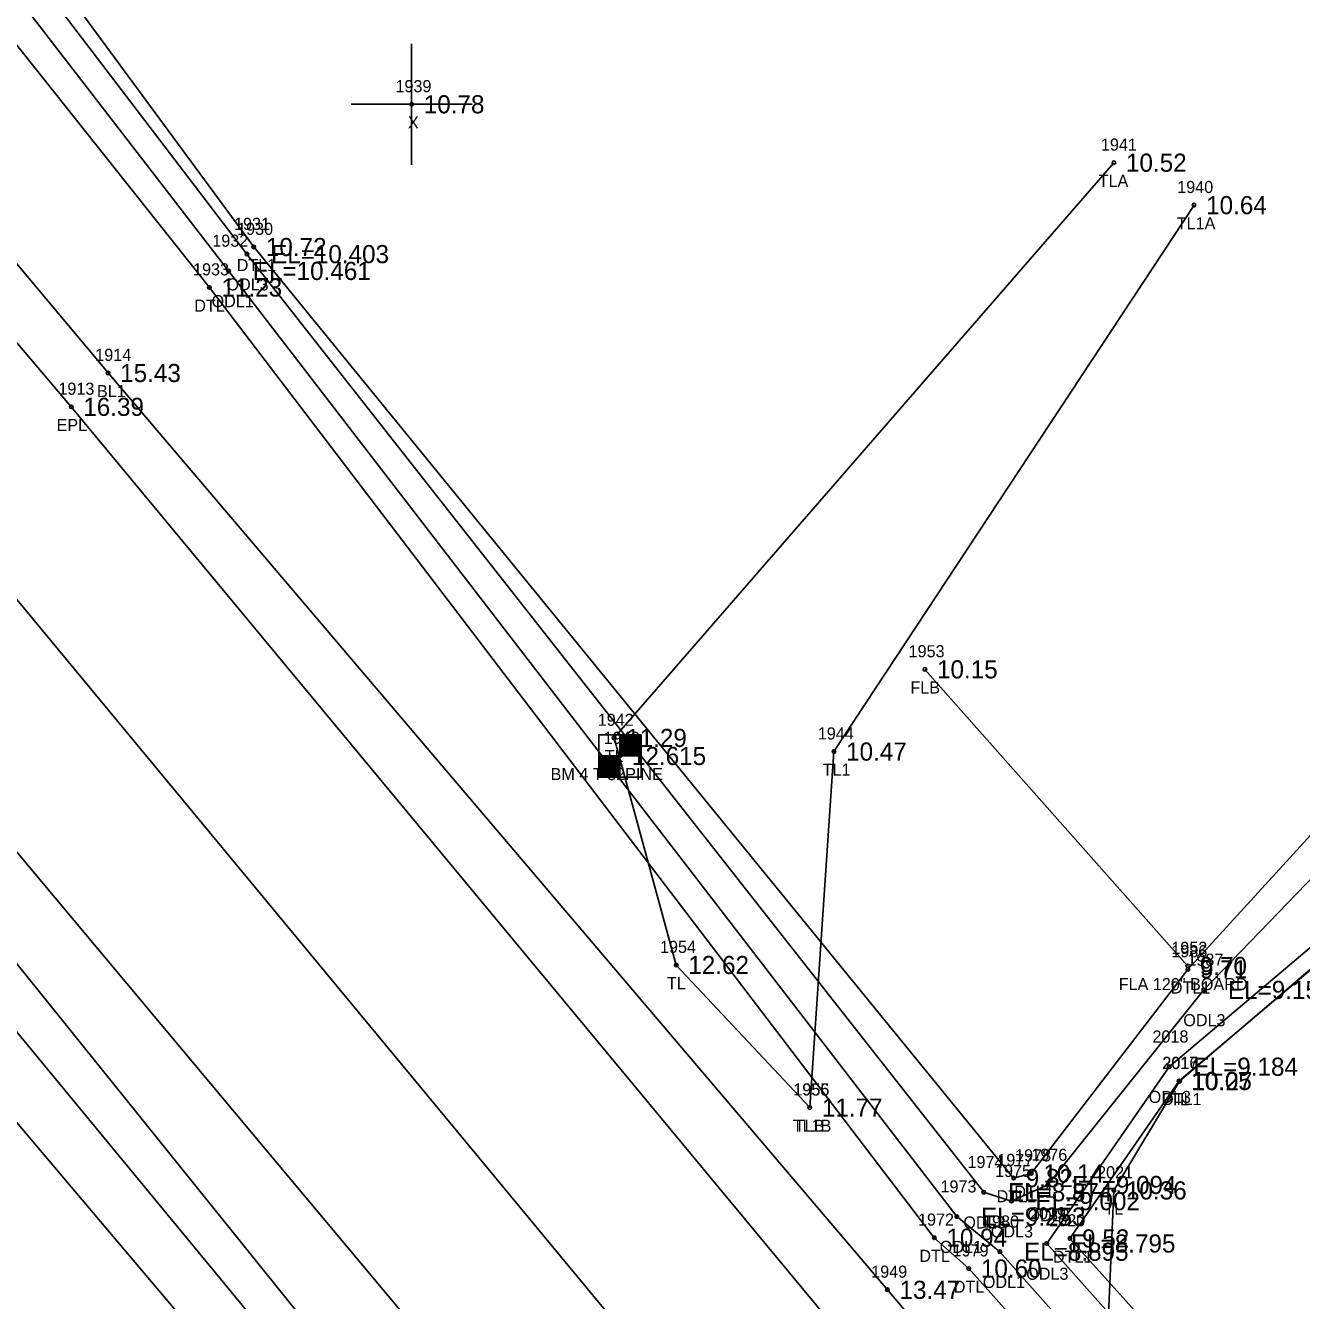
# Model space of a CAD drawing. Extents: x 2042211 to 2045853, y 303080 to 309569.
# Drawn here: x 2044074.2 to 2044179.7, y 305120.2 to 305225.7 of the extents above; entities that cross this region are included whole.
import ezdxf

# ---------------------------------------------------------------- set-up
doc = ezdxf.new("R2010")
doc.units = 0
for name, color, linetype in [('BR_500YR_SCOUR', 7, 'Continuous'), ('RD_DTM_BkLn1', 7, 'Continuous'), ('RD_DTM_BkLn2', 7, 'Continuous'), ('RD_DTM_BkLn_txCode', 7, 'Continuous'), ('RD_EX_Fence_Other_txCode', 7, 'Continuous'), ('RD_EX_H2O', 7, 'Continuous'), ('RD_EX_H2O_txCode', 7, 'Continuous'), ('RD_EX_Misc', 7, 'Continuous'), ('RD_EX_Misc_txCode', 7, 'Continuous'), ('RD_EX_Road', 7, 'Continuous'), ('RD_EX_Road_txCode', 7, 'Continuous'), ('RD_EX_TX_Fence_Other_ELEV', 7, 'Continuous'), ('RD_EX_TX_H2O_ELEV', 7, 'Continuous'), ('RD_EX_TX_Misc_ELEV', 7, 'Continuous'), ('RD_EX_TX_Road_ELEV', 7, 'Continuous'), ('RD_EX_TX_VEG_ELEV', 7, 'Continuous'), ('RD_EX_VEG_txCode', 7, 'Continuous'), ('RD_HC_Survey_ELEV', 7, 'Continuous'), ('RD_HC_Survey_txCode', 7, 'Continuous'), ('RD_SMD_Locator', 7, 'Continuous')]:
    doc.layers.add(name, color=color, linetype=linetype)

msp = doc.modelspace()

# ---------------------------------------------------------------- linework, layer by layer
at = {"layer": 'BR_500YR_SCOUR'}
for p, q in [((2044170.31, 305147.91), (2044148.58, 305172.44)), ((2044123.35, 305167.03), (2044123.35, 305163.53)), ((2044123.37, 305167.03), (2044123.37, 305165.28)), ((2044123.39, 305167.03), (2044123.39, 305165.28)), ((2044123.42, 305167.03), (2044123.42, 305165.28)), ((2044123.44, 305167.03), (2044123.44, 305165.28)), ((2044123.47, 305167.03), (2044123.47, 305165.28)), ((2044123.49, 305167.03), (2044123.49, 305165.28)), ((2044123.52, 305167.03), (2044123.52, 305165.28)), ((2044123.54, 305167.03), (2044123.54, 305165.28)), ((2044123.57, 305167.03), (2044123.57, 305165.28)), ((2044123.59, 305167.03), (2044123.59, 305165.28)), ((2044123.62, 305167.03), (2044123.62, 305165.28)), ((2044123.64, 305167.03), (2044123.64, 305165.28)), ((2044123.67, 305167.03), (2044123.67, 305165.28)), ((2044123.69, 305167.03), (2044123.69, 305165.28)), ((2044123.72, 305167.03), (2044123.72, 305165.28)), ((2044123.74, 305167.03), (2044123.74, 305165.28)), ((2044123.77, 305167.03), (2044123.77, 305165.28)), ((2044123.79, 305167.03), (2044123.79, 305165.28)), ((2044123.82, 305167.03), (2044123.82, 305165.28)), ((2044123.84, 305167.03), (2044123.84, 305165.28)), ((2044123.87, 305167.03), (2044123.87, 305165.28)), ((2044123.89, 305167.03), (2044123.89, 305165.28)), ((2044123.91, 305167.03), (2044123.91, 305165.28)), ((2044123.94, 305167.03), (2044123.94, 305165.28)), ((2044123.96, 305167.03), (2044123.96, 305165.28)), ((2044123.99, 305167.03), (2044123.99, 305165.28)), ((2044124.01, 305167.03), (2044124.01, 305165.28)), ((2044124.04, 305167.03), (2044124.04, 305165.28)), ((2044124.06, 305167.03), (2044124.06, 305165.28)), ((2044124.09, 305167.03), (2044124.09, 305165.28)), ((2044124.11, 305167.03), (2044124.11, 305165.28)), ((2044124.14, 305167.03), (2044124.14, 305165.28)), ((2044124.16, 305167.03), (2044124.16, 305165.28)), ((2044124.19, 305167.03), (2044124.19, 305165.28)), ((2044124.21, 305167.03), (2044124.21, 305165.28)), ((2044124.24, 305167.03), (2044124.24, 305165.28)), ((2044124.26, 305167.03), (2044124.26, 305165.28)), ((2044124.29, 305167.03), (2044124.29, 305165.28)), ((2044124.31, 305167.03), (2044124.31, 305165.28)), ((2044124.34, 305167.03), (2044124.34, 305165.28)), ((2044124.36, 305167.03), (2044124.36, 305165.28)), ((2044124.38, 305167.03), (2044124.38, 305165.28)), ((2044124.41, 305167.03), (2044124.41, 305165.28)), ((2044124.43, 305167.03), (2044124.43, 305165.28)), ((2044124.46, 305167.03), (2044124.46, 305165.28)), ((2044124.48, 305167.03), (2044124.48, 305165.28)), ((2044124.51, 305167.03), (2044124.51, 305165.28)), ((2044124.53, 305167.03), (2044124.53, 305165.28)), ((2044124.56, 305167.03), (2044124.56, 305165.28)), ((2044124.58, 305167.03), (2044124.58, 305165.28)), ((2044124.61, 305167.03), (2044124.61, 305165.28)), ((2044124.63, 305167.03), (2044124.63, 305165.28)), ((2044124.66, 305167.03), (2044124.66, 305165.28)), ((2044124.68, 305167.03), (2044124.68, 305165.28)), ((2044124.71, 305167.03), (2044124.71, 305165.28)), ((2044124.73, 305167.03), (2044124.73, 305165.28)), ((2044124.76, 305167.03), (2044124.76, 305165.28)), ((2044124.78, 305167.03), (2044124.78, 305165.28)), ((2044124.81, 305167.03), (2044124.81, 305165.28)), ((2044124.83, 305167.03), (2044124.83, 305165.28)), ((2044124.86, 305167.03), (2044124.86, 305165.28)), ((2044124.88, 305167.03), (2044124.88, 305165.28)), ((2044124.9, 305167.03), (2044124.9, 305165.28)), ((2044124.93, 305167.03), (2044124.93, 305165.28)), ((2044124.95, 305167.03), (2044124.95, 305165.28)), ((2044124.98, 305167.03), (2044124.98, 305165.28)), ((2044125, 305167.03), (2044125, 305165.28)), ((2044125.03, 305167.03), (2044125.03, 305165.28)), ((2044125.05, 305167.03), (2044125.05, 305165.28)), ((2044125.08, 305167.03), (2044125.08, 305165.28)), ((2044125.1, 305165.28), (2044121.6, 305165.28)), ((2044121.6, 305165.28), (2044121.6, 305163.53)), ((2044121.63, 305165.28), (2044121.63, 305163.53)), ((2044121.65, 305165.28), (2044121.65, 305163.53)), ((2044121.68, 305165.28), (2044121.68, 305163.53)), ((2044121.7, 305165.28), (2044121.7, 305163.53)), ((2044121.73, 305165.28), (2044121.73, 305163.53)), ((2044121.75, 305165.28), (2044121.75, 305163.53)), ((2044121.78, 305165.28), (2044121.78, 305163.53)), ((2044121.8, 305165.28), (2044121.8, 305163.53)), ((2044121.83, 305165.28), (2044121.83, 305163.53)), ((2044121.85, 305165.28), (2044121.85, 305163.53)), ((2044121.87, 305165.28), (2044121.87, 305163.53)), ((2044121.9, 305165.28), (2044121.9, 305163.53)), ((2044121.92, 305165.28), (2044121.92, 305163.53)), ((2044121.95, 305165.28), (2044121.95, 305163.53)), ((2044121.97, 305165.28), (2044121.97, 305163.53)), ((2044122, 305165.28), (2044122, 305163.53)), ((2044122.02, 305165.28), (2044122.02, 305163.53)), ((2044122.05, 305165.28), (2044122.05, 305163.53)), ((2044122.07, 305165.28), (2044122.07, 305163.53)), ((2044122.1, 305165.28), (2044122.1, 305163.53)), ((2044122.12, 305165.28), (2044122.12, 305163.53)), ((2044122.15, 305165.28), (2044122.15, 305163.53)), ((2044122.17, 305165.28), (2044122.17, 305163.53)), ((2044122.2, 305165.28), (2044122.2, 305163.53)), ((2044122.22, 305165.28), (2044122.22, 305163.53)), ((2044122.25, 305165.28), (2044122.25, 305163.53)), ((2044122.27, 305165.28), (2044122.27, 305163.53)), ((2044122.3, 305165.28), (2044122.3, 305163.53)), ((2044122.32, 305165.28), (2044122.32, 305163.53)), ((2044122.34, 305165.28), (2044122.34, 305163.53)), ((2044122.37, 305165.28), (2044122.37, 305163.53)), ((2044122.39, 305165.28), (2044122.39, 305163.53)), ((2044122.42, 305165.28), (2044122.42, 305163.53)), ((2044122.44, 305165.28), (2044122.44, 305163.53)), ((2044122.47, 305165.28), (2044122.47, 305163.53)), ((2044122.49, 305165.28), (2044122.49, 305163.53)), ((2044122.52, 305165.28), (2044122.52, 305163.53)), ((2044122.54, 305165.28), (2044122.54, 305163.53)), ((2044122.57, 305165.28), (2044122.57, 305163.53)), ((2044122.59, 305165.28), (2044122.59, 305163.53)), ((2044122.62, 305165.28), (2044122.62, 305163.53)), ((2044122.64, 305165.28), (2044122.64, 305163.53)), ((2044122.67, 305165.28), (2044122.67, 305163.53)), ((2044122.69, 305165.28), (2044122.69, 305163.53)), ((2044122.72, 305165.28), (2044122.72, 305163.53)), ((2044122.74, 305165.28), (2044122.74, 305163.53)), ((2044122.77, 305165.28), (2044122.77, 305163.53)), ((2044122.79, 305165.28), (2044122.79, 305163.53)), ((2044122.82, 305165.28), (2044122.82, 305163.53)), ((2044122.84, 305165.28), (2044122.84, 305163.53)), ((2044122.86, 305165.28), (2044122.86, 305163.53)), ((2044122.89, 305165.28), (2044122.89, 305163.53)), ((2044122.91, 305165.28), (2044122.91, 305163.53)), ((2044122.94, 305165.28), (2044122.94, 305163.53)), ((2044122.96, 305165.28), (2044122.96, 305163.53)), ((2044122.99, 305165.28), (2044122.99, 305163.53)), ((2044123.01, 305165.28), (2044123.01, 305163.53)), ((2044123.04, 305165.28), (2044123.04, 305163.53)), ((2044123.06, 305165.28), (2044123.06, 305163.53)), ((2044123.09, 305165.28), (2044123.09, 305163.53)), ((2044123.11, 305165.28), (2044123.11, 305163.53)), ((2044123.14, 305165.28), (2044123.14, 305163.53)), ((2044123.16, 305165.28), (2044123.16, 305163.53)), ((2044123.19, 305165.28), (2044123.19, 305163.53)), ((2044123.21, 305165.28), (2044123.21, 305163.53)), ((2044123.24, 305165.28), (2044123.24, 305163.53)), ((2044123.26, 305165.28), (2044123.26, 305163.53)), ((2044123.29, 305165.28), (2044123.29, 305163.53)), ((2044123.31, 305165.28), (2044123.31, 305163.53)), ((2044123.33, 305165.28), (2044123.33, 305163.53))]:
    msp.add_line(p, q, dxfattribs=at)
for points in [[(2043981.22, 305231.74), (2043985.09, 305231.71), (2043988, 305235.21), (2044050.29, 305170.52), (2044112.48, 305095.16), (2044104.33, 305083.55)], [(2044164.21, 305214.34), (2044122.87, 305166.77), (2044128.01, 305147.99), (2044139.06, 305136.2)], [(2044170.84, 305210.83), (2044141.06, 305165.64), (2044139.06, 305136.2)], [(2044203.29, 305185.8), (2044187.09, 305153.29), (2044169.64, 305138.38), (2044164.21, 305129.35), (2044163.7, 305117.76), (2044206.63, 305057.39), (2044230.52, 305052.69), (2044229.62, 305068.74), (2044231.4, 305092.87), (2044226.11, 305140.65)]]:
    msp.add_lwpolyline(points, dxfattribs=at)
msp.add_lwpolyline([(2044125.1, 305167.03), (2044121.6, 305167.03), (2044121.6, 305163.53), (2044125.1, 305163.53)], close=True, dxfattribs=at)
for centre in [(2044164.21, 305214.34), (2044170.84, 305210.83), (2044122.87, 305166.77), (2044123.35, 305165.28), (2044141.06, 305165.64), (2044128.01, 305147.99), (2044169.64, 305138.38), (2044139.06, 305136.2), (2044164.21, 305129.35)]:
    msp.add_circle(centre, 0.15, dxfattribs=at)
at = {"layer": 'RD_DTM_BkLn1'}
for points in [[(2043537.57, 305841.2), (2043543.07, 305834.82), (2043547.67, 305836.32), (2043557.54, 305825.5), (2043571.92, 305809.49), (2043633.83, 305732.88), (2043699.09, 305656.29), (2043762.93, 305580.55), (2043827.21, 305502.36), (2043888.69, 305425.33), (2043954.53, 305349.45), (2044014.08, 305277.47), (2044018.49, 305276.45), (2044019.61, 305275.44), (2044023.1, 305269.64), (2044024.11, 305264.85), (2044081.02, 305196.95), (2044145.48, 305121.13), (2044210.56, 305044.49), (2044273.6, 304967.95), (2044321.18, 304912.75), (2044337.82, 304895.78)], [(2043528.91, 305830.2), (2043556.35, 305797.19), (2043619.96, 305720.85), (2043684.02, 305644.21), (2043747.98, 305567.9), (2043812.35, 305491.13), (2043876, 305414.64), (2043940.22, 305337.83), (2044003.86, 305261.82), (2044067.88, 305184.94), (2044131, 305108.73), (2044195.62, 305032.03), (2044259.59, 304955.88), (2044323.63, 304879.52), (2044387.48, 304802.4), (2044451.92, 304725.21), (2044515.94, 304648.42), (2044581.15, 304571.52), (2044645.01, 304495.17), (2044708.42, 304418.52), (2044772.84, 304341.13)], [(2043798.36, 305479.17), (2043862.32, 305402.71), (2043926.37, 305326.69), (2043989.74, 305249.79), (2043988.33, 305246.75), (2043991.19, 305243.51), (2043994.75, 305243.65), (2044053.09, 305173.37), (2044116.28, 305094.9), (2044180.2, 305019.52), (2044245.63, 304943.51), (2044308.37, 304866.05), (2044373.1, 304789.96), (2044438.35, 304712.62), (2044501.57, 304636.05), (2044528.47, 304600.32), (2044565.87, 304558.85), (2044630.47, 304482.97), (2044694.06, 304405.2), (2044697.06, 304397.81), (2044701.81, 304392.08), (2044707.96, 304388.87), (2044759.04, 304329.78)]]:
    msp.add_lwpolyline(points, dxfattribs=at)
at = {"layer": 'RD_DTM_BkLn2'}
msp.add_lwpolyline([(2043985.04, 305231.73), (2044045.47, 305168.04), (2044111.06, 305090.52)], dxfattribs=at)
at = {"layer": 'RD_EX_H2O'}
for points in [[(2043695.41, 305785.95), (2043753.23, 305702.74), (2043816.84, 305621.67), (2043878.98, 305542.47), (2043936.42, 305466.41), (2044001.08, 305383.06), (2044036.64, 305336.24), (2044042.32, 305312.25), (2044044.08, 305296.68), (2044037.04, 305284.58), (2044037.23, 305281.89), (2044040.11, 305279.62), (2044044.74, 305276.06), (2044050.89, 305261.28), (2044092.5, 305206.78), (2044153.45, 305129.2), (2044155.72, 305128.46), (2044158.75, 305129.8), (2044171.64, 305145.93), (2044183.17, 305157.87), (2044199.16, 305188.17), (2044208.66, 305215.31)], [(2044033.22, 305275.98), (2044035.9, 305278.5), (2044040.04, 305277.28), (2044042.29, 305273.95), (2044048.6, 305260.29), (2044090.99, 305205.39), (2044151.22, 305127.18), (2044154.78, 305124.28), (2044202.92, 305070.22), (2044216.63, 305053.71), (2044279.58, 304974.12), (2044337.99, 304907.57), (2044344.68, 304901.99)], [(2044036.31, 305275.77), (2044038.93, 305275.76), (2044040.37, 305274.17), (2044045.78, 305258.87), (2044089.4, 305204.02), (2044149.36, 305125.44), (2044152.21, 305122.89), (2044203.11, 305065.8), (2044214.18, 305051.6), (2044278.81, 304973.18), (2044336.46, 304906.31), (2044343.82, 304899.94), (2044347.6, 304901.86)], [(2044052.64, 305262.28), (2044093.07, 305207.37), (2044155.92, 305130.37), (2044157.38, 305130.75), (2044170.33, 305147.63), (2044181.38, 305159.73), (2044197.15, 305188.95), (2044208.08, 305219.28), (2044210.72, 305219.24), (2044215.12, 305217.08), (2044202.83, 305184.83), (2044185.43, 305151.79), (2044169.6, 305138.4), (2044160.58, 305125.38), (2044211.54, 305068.64), (2044219.9, 305056.44), (2044285.19, 304978.84), (2044339.94, 304911.4), (2044347.53, 304904.82), (2044347.6, 304901.86)], [(2044211.75, 305214.4), (2044200.54, 305185.5), (2044183.75, 305152.21), (2044168.79, 305139.58), (2044158.66, 305124.96), (2044210.53, 305066.67), (2044218.51, 305055.53), (2044282.21, 304976.06), (2044339.42, 304909.19), (2044345.98, 304903.69)]]:
    msp.add_lwpolyline(points, dxfattribs=at)
at = {"layer": 'RD_EX_Misc'}
for p, q in [((2044106.13, 305214.17), (2044106.13, 305224.17)), ((2044101.13, 305219.17), (2044111.13, 305219.17))]:
    msp.add_line(p, q, dxfattribs=at)
at = {"layer": 'RD_EX_Road'}
for points in [[(2043522.11, 305820), (2043547.67, 305789.85), (2043610.72, 305713.32), (2043674.95, 305636.32), (2043738.18, 305559.62), (2043802.42, 305482.71), (2043865.72, 305405.84), (2043929.53, 305328.85), (2043994.13, 305253.28), (2044057.4, 305176.5), (2044121.27, 305100.2), (2044185.29, 305023.54), (2044249.56, 304947.28), (2044313.31, 304870.31), (2044377.09, 304793.29), (2044442, 304716.26), (2044505.92, 304639.55), (2044570.44, 304562.35), (2044634.61, 304485.93), (2044698.46, 304409.27), (2044762.46, 304332.37)], [(2044013.41, 305270.34), (2044077.97, 305194.15), (2044141.4, 305117.67), (2044205.92, 305040.83), (2044269.54, 304964.65), (2044331.73, 304891.04), (2044335.22, 304889.2), (2044346.01, 304875.31), (2044356.18, 304867.61), (2044370.01, 304868.14), (2044386.83, 304866.36), (2044389.44, 304849.53), (2044390.71, 304830.73), (2044393.77, 304818.44), (2044395.5, 304814.18), (2044398.16, 304811.09), (2044461.8, 304734.03), (2044526.04, 304657.6), (2044591.28, 304580.23), (2044655.29, 304503.62), (2044718.26, 304427.32), (2044783.13, 304349.86)]]:
    msp.add_lwpolyline(points, dxfattribs=at)
at = {"layer": 'RD_SMD_Locator'}
for centre in [(2044106.13, 305219.17), (2044093.07, 305207.37), (2044092.5, 305206.78), (2044090.99, 305205.39), (2044089.4, 305204.02), (2044081.02, 305196.95), (2044077.97, 305194.15), (2044148.58, 305172.44), (2044170.31, 305147.91), (2044170.33, 305147.63), (2044171.64, 305145.93), (2044168.79, 305139.58), (2044169.6, 305138.4), (2044139.06, 305136.2), (2044155.92, 305130.37), (2044157.38, 305130.75), (2044153.45, 305129.2), (2044158.75, 305129.8), (2044155.72, 305128.46), (2044151.22, 305127.18), (2044149.36, 305125.44), (2044158.66, 305124.96), (2044160.58, 305125.38), (2044154.78, 305124.28), (2044152.21, 305122.89), (2044145.48, 305121.13)]:
    msp.add_circle(centre, 0.15, dxfattribs=at)

# ---------------------------------------------------------------- texts
at = {"layer": 'RD_DTM_BkLn_txCode'}
for s, p in [('1914', (2044079.96, 305197.95)), ('BL1', (2044080.1, 305194.95)), ('1949', (2044144.14, 305122.13))]:
    msp.add_text(s, height=1, dxfattribs=at).set_placement(p)
at = {"layer": 'RD_EX_Fence_Other_txCode'}
for s, p in [('1953', (2044147.23, 305173.44)), ('FLB', (2044147.38, 305170.44)), ('1952', (2044168.96, 305148.91)), ('FLA 120" BOARD', (2044164.61, 305145.91))]:
    msp.add_text(s, height=1, dxfattribs=at).set_placement(p)
at = {"layer": 'RD_EX_H2O_txCode'}
for s, p in [('1931', (2044091.44, 305208.78)), ('1930', (2044091.69, 305208.37)), ('1932', (2044089.64, 305207.39)), ('DTL1', (2044091.66, 305205.37)), ('1933', (2044088.05, 305205.02)), ('ODL3', (2044090.81, 305203.78)), ('ODL1', (2044089.58, 305202.39)), ('DTL', (2044088.15, 305202.02)), ('1986', (2044168.96, 305148.63)), ('1987', (2044170.29, 305147.93)), ('DTL1', (2044168.92, 305145.63)), ('ODL3', (2044169.95, 305142.93)), ('2018', (2044167.4, 305141.58)), ('2017', (2044168.21, 305139.4)), ('ODL3', (2044167.09, 305136.58)), ('DTL1', (2044168.19, 305136.4)), ('1978', (2044156.04, 305131.75)), ('1976', (2044157.38, 305131.8)), ('1974', (2044152.1, 305131.2)), ('1975', (2044154.38, 305130.46)), ('1977', (2044154.57, 305131.37)), ('1973', (2044149.87, 305129.18)), ('DTL1', (2044154.51, 305128.37)), ('DTL1', (2044155.97, 305128.75)), ('1972', (2044148.01, 305126.44)), ('ODL3', (2044151.76, 305126.2)), ('1980', (2044153.39, 305126.28)), ('ODL3', (2044157.06, 305126.8)), ('2019', (2044157.27, 305126.96)), ('2020', (2044158.87, 305126.38)), ('ODL3', (2044154.03, 305125.46)), ('ODL1', (2044149.81, 305124.18)), ('DTL', (2044148.12, 305123.44)), ('1979', (2044150.87, 305123.89)), ('DTL1', (2044159.17, 305123.38)), ('ODL3', (2044156.96, 305121.96)), ('DTL', (2044150.97, 305120.89)), ('ODL1', (2044153.37, 305121.28))]:
    msp.add_text(s, height=1, dxfattribs=at).set_placement(p)
at = {"layer": 'RD_EX_Misc_txCode'}
for s, p in [('1939', (2044104.79, 305220.17)), ('X', (2044105.82, 305217.17))]:
    msp.add_text(s, height=1, dxfattribs=at).set_placement(p)
at = {"layer": 'RD_EX_Road_txCode'}
for s, p in [('1913', (2044076.91, 305195.15)), ('EPL', (2044076.76, 305192.15))]:
    msp.add_text(s, height=1, dxfattribs=at).set_placement(p)
at = {"layer": 'RD_EX_TX_Fence_Other_ELEV'}
for s, p in [('10.15', (2044149.58, 305171.69)), ('9.70', (2044171.31, 305147.16))]:
    msp.add_text(s, height=1.5, dxfattribs=at).set_placement(p)
at = {"layer": 'RD_EX_TX_H2O_ELEV'}
for s, p in [('10.72', (2044094.07, 305206.62)), ('EL=10.403', (2044094.5, 305206.03)), ('EL=10.461', (2044092.99, 305204.64)), ('11.23', (2044090.4, 305203.27)), ('9.71', (2044171.33, 305146.88)), ('EL=9.150', (2044173.64, 305145.18)), ('EL=9.184', (2044170.79, 305138.83)), ('10.05', (2044170.6, 305137.65)), ('10.14', (2044158.38, 305130)), ('9.82', (2044156.92, 305129.62)), ('EL=9.094', (2044160.75, 305129.05)), ('EL=8.874', (2044155.45, 305128.45)), ('EL=9.002', (2044157.72, 305127.71)), ('EL=9.253', (2044153.22, 305126.43)), ('10.94', (2044150.36, 305124.69)), ('9.52', (2044161.58, 305124.63)), ('EL=8.895', (2044156.78, 305123.53)), ('EL=8.795', (2044160.66, 305124.21)), ('10.60', (2044153.21, 305122.14))]:
    msp.add_text(s, height=1.5, dxfattribs=at).set_placement(p)
at = {"layer": 'RD_EX_TX_Misc_ELEV'}
for s, p in [('10.78', (2044107.13, 305218.42)), ('15.43', (2044082.02, 305196.2)), ('13.47', (2044146.48, 305120.38))]:
    msp.add_text(s, height=1.5, dxfattribs=at).set_placement(p)
at = {"layer": 'RD_EX_TX_Road_ELEV'}
msp.add_text('16.39', height=1.5, dxfattribs=at).set_placement((2044078.97, 305193.4))
at = {"layer": 'RD_EX_TX_VEG_ELEV'}
for s, p in [('10.52', (2044165.21, 305213.59)), ('10.64', (2044171.84, 305210.08)), ('11.29', (2044123.87, 305166.02)), ('10.47', (2044142.06, 305164.89)), ('12.62', (2044129.01, 305147.24)), ('10.27', (2044170.64, 305137.63)), ('11.77', (2044140.06, 305135.45)), ('11.77', (2044140.06, 305135.45)), ('10.36', (2044165.21, 305128.6))]:
    msp.add_text(s, height=1.5, dxfattribs=at).set_placement(p)
at = {"layer": 'RD_EX_VEG_txCode'}
for s, p in [('1941', (2044163.14, 305215.34)), ('TLA', (2044162.95, 305212.34)), ('1940', (2044169.45, 305211.83)), ('TL1A', (2044169.41, 305208.83)), ('1942', (2044121.52, 305167.77)), ('1944', (2044139.72, 305166.64)), ('TL', (2044122.1, 305164.77)), ('TL1', (2044140.12, 305163.64)), ('1954', (2044126.67, 305148.99)), ('TL', (2044127.24, 305145.99)), ('2016', (2044168.23, 305139.38)), ('1956', (2044137.69, 305137.2)), ('1955', (2044137.71, 305137.2)), ('TL', (2044168.87, 305136.38)), ('TL1B', (2044137.65, 305134.2)), ('TLB', (2044137.81, 305134.2)), ('2021', (2044162.82, 305130.35)), ('TL', (2044163.43, 305127.35))]:
    msp.add_text(s, height=1, dxfattribs=at).set_placement(p)
at = {"layer": 'RD_HC_Survey_ELEV'}
msp.add_text('12.615', height=1.5, dxfattribs=at).set_placement((2044124.35, 305164.53))
at = {"layer": 'RD_HC_Survey_txCode'}
for s, p in [('1943', (2044122.01, 305166.28)), ('BM 4 T 32PINE', (2044117.62, 305163.28))]:
    msp.add_text(s, height=1, dxfattribs=at).set_placement(p)

doc.saveas('drawing.dxf')
